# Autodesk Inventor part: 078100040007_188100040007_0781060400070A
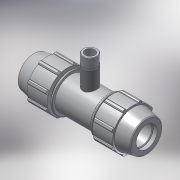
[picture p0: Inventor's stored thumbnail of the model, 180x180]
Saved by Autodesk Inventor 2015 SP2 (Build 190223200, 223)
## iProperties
Created: 2017-02
Part Number: 078100040007_188100040007_0781060400070A
Material: PVC-Piping
Description: PLASSON COUPLER WITH RISER 40-3/4"
Document SubType Name: Modeling
Designer: KIM
Mass: 92.6774 g
Surface Area: 199.44 cm^2
Volume: 66.1981 cm^3
Density: 1.4 g/cm^3
Appearance: Smooth - White
Author: Кирилл
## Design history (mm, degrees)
derived "07810.ipt"
feature "Solid1::07810.ipt"
feature "Solid2::07810.ipt"
tag "TaggingFeature1"
body "Solid1"
other parameters: "d4" = 8.95833, "d5" = 25.8, "d7" = 82, "d11" = 3.58333, "d13" = 120 deg, "d15" = 12 deg, "d16" = 71.34, "d18" = 2, "d19" = 35 deg, "d20" = 17.5 deg, "d21" = 76.26, "d23" = 0, "d25" = 360 deg, "d27" = 1.64, "d33" = 0.8, "d42" = 38.7, "d43" = 2.46, "d46" = 1.2, "d68" = 3.58333, "d72" = 85, "d73" = 26.441, "d74" = 18, "d76" = 18.5087, "d77" = 21.6, "d80" = 0.79323, "d91" = 61.5, "d93" = 89, "d95" = 36, "d99" = 215, "d101" = 0, "d103" = 0, "d105" = 0, "d106" = 26.96982, "E_" = 82, "A_" = 85, "l_" = 89, "l_2" = 18, "H_" = 215, "R_" = 26.441
